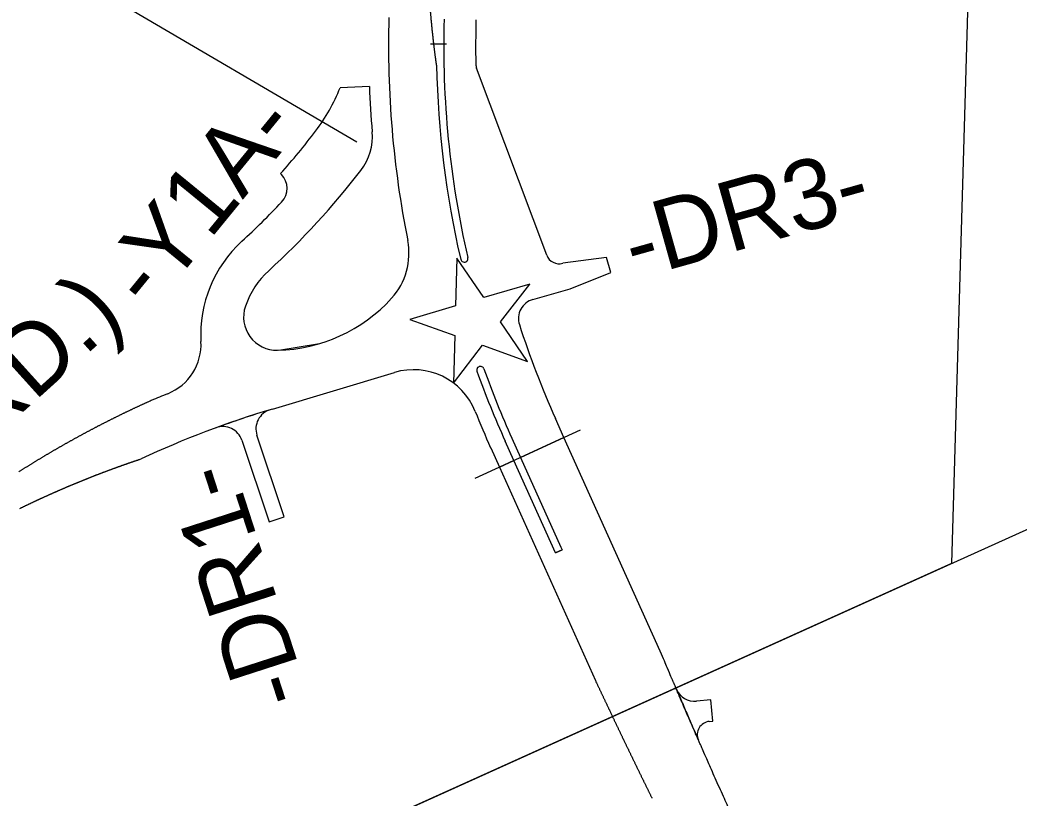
# Model space of a CAD drawing. Extents: x 2094564 to 2100382, y 679033 to 692366.
# Drawn here: x 2097390 to 2098142, y 685528 to 686113 of the extents above; entities that cross this region are included whole.
import ezdxf

# ---------------------------------------------------------------- set-up
doc = ezdxf.new("R2010")
doc.units = 0
for name, color, linetype in [('Pattern 17', 7, 'Continuous'), ('Prop RDY Traffic Signal CELL', 7, 'Continuous'), ('Prop Shade Light', 7, 'Continuous'), ('Scratch_Level_0', 7, 'Continuous'), ('Scratch_Level_1', 7, 'Continuous'), ('Scratch_Level_3', 7, 'Continuous')]:
    doc.layers.add(name, color=color, linetype=linetype)

msp = doc.modelspace()

# ---------------------------------------------------------------- linework, layer by layer
at = {"layer": 'Pattern 17'}
for points in [[(2098090.85, 685704.42), (2097236.93, 685318.96), (2097029.37, 685324.99), (2097061.33, 686424.42), (2097067.15, 686624.39), (2097093.39, 686623.63), (2097228.13, 686619.71), (2097231.42, 686732.99), (2098120, 686707.16)], [(2098911.14, 684517.12), (2097955.44, 684082.23), (2097499.89, 685083.35), (2097417.03, 685265.44), (2097440.93, 685276.32), (2097563.62, 685332.14), (2097512.93, 685443.54), (2098323.16, 685809.28)]]:
    msp.add_lwpolyline(points, close=True, dxfattribs=at)
at = {"layer": 'Prop RDY Traffic Signal CELL'}
msp.add_lwpolyline([(2097739.08, 685904.5), (2097718.8, 685934.13), (2097717.79, 685898.24), (2097683.27, 685888.09), (2097717.17, 685876.01), (2097716.16, 685840.07), (2097738.1, 685868.55), (2097771.95, 685856.48), (2097751.65, 685886.14), (2097773.61, 685914.65), (2097739.08, 685904.5)], dxfattribs=at)
at = {"layer": 'Prop Shade Light'}
for p, q in [((2097786.31, 685936.39), (2097733.62, 686076.93)), ((2097652.95, 686063.22), (2097630.92, 686062.34)), ((2097586.14, 685997.68), (2097586.79, 685997)), ((2097831.27, 685934.7), (2097798.4, 685930.28)), ((2097834.47, 685923.42), (2097831.27, 685934.7)), ((2097803.86, 685911.04), (2097834.47, 685923.42)), ((2097775.95, 685903.12), (2097803.86, 685911.04)), ((2097584.79, 685864.84), (2097615.37, 685869.82)), ((2097580, 685820.61), (2097671.8, 685848.08)), ((2097799.34, 685799.25), (2097792.96, 685813.43)), ((2097556.97, 685797.17), (2097577.46, 685735.81)), ((2097588.84, 685739.61), (2097568.35, 685800.97)), ((2097761.62, 685781.95), (2097755.12, 685796.4)), ((2097760.13, 685798.66), (2097766.62, 685784.24)), ((2097799.34, 685799.25), (2097766.62, 685784.24)), ((2097766.62, 685784.24), (2097799.34, 685799.25)), ((2097871.74, 685638.39), (2097799.34, 685799.25)), ((2097744.18, 685791.48), (2097750.72, 685776.94)), ((2097761.62, 685781.95), (2097750.72, 685776.94)), ((2097750.72, 685776.94), (2097761.62, 685781.95)), ((2097792.84, 685712.58), (2097761.62, 685781.95)), ((2097766.62, 685784.24), (2097797.05, 685716.63)), ((2097750.72, 685776.94), (2097822.96, 685616.43)), ((2097577.46, 685735.81), (2097588.84, 685739.61)), ((2097797.87, 685714.8), (2097792.84, 685712.58)), ((2097797.05, 685716.63), (2097797.87, 685714.8)), ((2097909.76, 685601.83), (2097899.1, 685600.84)), ((2097911.25, 685585.9), (2097909.76, 685601.83)), ((2097908.66, 685585.66), (2097911.25, 685585.9))]:
    msp.add_line(p, q, dxfattribs=at)
msp.add_lwpolyline([(2097646.53, 686000.13), (2097646.53, 686000.13)], dxfattribs=at)
for centre, radius, start, end in [((2098415.1, 686093.44), 747.75, 178.33483, 191.26257), ((2098415.1, 686093.44), 706.25, 178.33483, 193.00645), ((2098415.1, 686093.44), 682.25, 178.33483, 181.10817), ((2098415.1, 686093.44), 711.75, 181.14892, 193.00593), ((2097742.98, 686080.44), 10, 181.10817, 200.55266), ((2097503.07, 686112.96), 137.5, 322.71885, 338.39952), ((2098415.1, 686093.44), 762.75, 182.27079, 184.83226), ((2097180.74, 686358.34), 542.6, 318.34184, 322.71885), ((2097613.34, 686025.66), 41.88, 322.43812, 4.83226), ((2097180.74, 686358.34), 587.6, 312.43424, 322.43799), ((2097575.99, 685986.59), 15, 316.75473, 43.94176), ((2097180.74, 686358.34), 557.6, 312.43424, 316.75473), ((2097621.08, 685876.69), 95, 132.43424, 183.15611), ((2097632.72, 685937.63), 50, 317.65988, 11.26257), ((2097724.29, 685933.87), 2.75, 192.87166, 13.00645), ((2097795.67, 685939.9), 10, 200.55266, 285.83492), ((2097621.08, 685876.69), 65, 132.43424, 160.85001), ((2097580.98, 685984.78), 120, 271.39981, 317.65988), ((2097780.05, 685888.69), 15, 105.83492, 197.86981), ((2097583.3, 685889.81), 25, 160.85001, 271.39981), ((2098415.1, 686093.44), 682.25, 197.86981, 204.23092), ((2097486.29, 685869.26), 40, 291.99663, 3.15611), ((2097686.13, 685800.18), 50, 21.91468, 106.65716), ((2097736.46, 685849.97), 2.75, 19.63206, 199.73603), ((2098415.1, 686093.44), 723.75, 199.73603, 204.23092), ((2098415.1, 686093.44), 718.25, 199.73643, 204.23092), ((2097791.55, 685113.58), 775, 111.99663, 112.98788), ((2097791.55, 685113.58), 738, 106.65716, 114.87261), ((2097791.55, 685113.58), 738, 106.80013, 110.12898), ((2097582.58, 685805.72), 15, 106.80013, 198.46455), ((2098415.1, 686093.44), 735.75, 201.91468, 204.23092), ((2097542.74, 685792.42), 15, 18.46455, 110.12898), ((2097897.7, 685615.77), 15, 203.16029, 275.3551), ((2097909.59, 685575.7), 10, 95.3551, 203.63261)]:
    msp.add_arc(centre, radius, start, end, dxfattribs=at)
for points in [[(2097699.61, 686112.47), (2097699.57, 686112.91), (2097699.5, 686113.58), (2097699.44, 686114.26), (2097699.38, 686114.94), (2097699.32, 686115.62), (2097699.26, 686116.3), (2097699.2, 686116.97), (2097699.13, 686117.65), (2097699.07, 686118.33), (2097699.01, 686119.01), (2097698.95, 686119.68), (2097698.89, 686120.36), (2097698.83, 686121.04), (2097698.77, 686121.72), (2097698.7, 686122.4), (2097698.64, 686123.07), (2097698.58, 686123.75), (2097698.52, 686124.43), (2097698.46, 686125.11), (2097698.4, 686125.78), (2097698.34, 686126.46), (2097698.27, 686127.14), (2097698.21, 686127.82), (2097698.15, 686128.49), (2097698.09, 686129.17)], [(2097701.35, 686095.8), (2097701.33, 686095.99), (2097701.25, 686096.66), (2097701.18, 686097.34), (2097701.1, 686098.01), (2097701.02, 686098.69), (2097700.95, 686099.37), (2097700.87, 686100.04), (2097700.8, 686100.72), (2097700.72, 686101.39), (2097700.65, 686102.07), (2097700.58, 686102.74), (2097700.51, 686103.42), (2097700.43, 686104.1), (2097700.36, 686104.77), (2097700.29, 686105.45), (2097700.22, 686106.13), (2097700.16, 686106.81), (2097700.09, 686107.48), (2097700.02, 686108.16), (2097699.95, 686108.84), (2097699.89, 686109.51), (2097699.82, 686110.19), (2097699.76, 686110.87), (2097699.69, 686111.55), (2097699.63, 686112.23), (2097699.61, 686112.47)], [(2097703.5, 686079.17), (2097703.4, 686079.84), (2097703.31, 686080.51), (2097703.22, 686081.18), (2097703.12, 686081.85), (2097703.03, 686082.52), (2097702.94, 686083.2), (2097702.85, 686083.87), (2097702.76, 686084.54), (2097702.67, 686085.21), (2097702.58, 686085.88), (2097702.5, 686086.56), (2097702.41, 686087.23), (2097702.32, 686087.9), (2097702.24, 686088.58), (2097702.15, 686089.25), (2097702.07, 686089.92), (2097701.98, 686090.6), (2097701.9, 686091.27), (2097701.82, 686091.94), (2097701.73, 686092.62), (2097701.65, 686093.29), (2097701.57, 686093.97), (2097701.49, 686094.64), (2097701.41, 686095.31), (2097701.35, 686095.8)], [(2097488.88, 685827.04), (2097487.21, 685826.29), (2097486.37, 685825.91), (2097485.53, 685825.53), (2097484.69, 685825.15), (2097483.86, 685824.77), (2097483.02, 685824.39), (2097482.19, 685824), (2097481.35, 685823.62), (2097480.52, 685823.24), (2097479.69, 685822.85), (2097478.85, 685822.46), (2097478.02, 685822.08), (2097477.19, 685821.69), (2097476.36, 685821.3), (2097475.52, 685820.91), (2097474.69, 685820.51), (2097473.86, 685820.12), (2097473.03, 685819.73), (2097472.2, 685819.33), (2097471.37, 685818.94), (2097470.55, 685818.54), (2097469.72, 685818.15), (2097468.89, 685817.75), (2097468.35, 685817.49)], [(2097468.35, 685817.49), (2097468.06, 685817.35), (2097467.24, 685816.95), (2097466.41, 685816.55), (2097465.59, 685816.14), (2097464.76, 685815.74), (2097463.94, 685815.34), (2097463.11, 685814.93), (2097462.29, 685814.52), (2097461.47, 685814.12), (2097460.64, 685813.71), (2097459.82, 685813.3), (2097459, 685812.89), (2097458.18, 685812.48), (2097457.36, 685812.07), (2097456.54, 685811.65), (2097455.72, 685811.24), (2097454.9, 685810.83), (2097454.08, 685810.41), (2097453.26, 685809.99), (2097452.45, 685809.58), (2097451.63, 685809.16), (2097450.81, 685808.74), (2097450, 685808.32), (2097449.18, 685807.9), (2097448.37, 685807.47), (2097448.11, 685807.34)], [(2097448.11, 685807.34), (2097447.55, 685807.05), (2097446.74, 685806.63), (2097445.93, 685806.2), (2097445.11, 685805.77), (2097444.3, 685805.35), (2097443.49, 685804.92), (2097442.68, 685804.49), (2097441.87, 685804.06), (2097441.06, 685803.63), (2097440.25, 685803.2), (2097439.44, 685802.76), (2097438.63, 685802.33), (2097437.82, 685801.89), (2097437.01, 685801.46), (2097436.21, 685801.02), (2097435.4, 685800.58), (2097434.6, 685800.15), (2097433.79, 685799.71), (2097432.99, 685799.27), (2097432.18, 685798.82), (2097431.38, 685798.38), (2097430.57, 685797.94), (2097429.77, 685797.49), (2097428.97, 685797.05), (2097428.17, 685796.6)], [(2097428.17, 685796.6), (2097427.37, 685796.16), (2097426.57, 685795.71), (2097425.77, 685795.26), (2097424.97, 685794.81), (2097424.17, 685794.36), (2097423.37, 685793.91), (2097422.57, 685793.45), (2097421.78, 685793), (2097420.98, 685792.54), (2097420.18, 685792.09), (2097419.39, 685791.63), (2097418.59, 685791.17), (2097417.8, 685790.72), (2097417.01, 685790.26), (2097416.21, 685789.8), (2097415.42, 685789.34), (2097414.63, 685788.87), (2097413.84, 685788.41), (2097413.05, 685787.95), (2097412.26, 685787.48), (2097411.47, 685787.02), (2097410.68, 685786.55), (2097409.89, 685786.08), (2097409.1, 685785.61), (2097408.59, 685785.31)], [(2097408.59, 685785.31), (2097408.31, 685785.14), (2097407.53, 685784.67), (2097406.74, 685784.2), (2097405.95, 685783.73), (2097405.17, 685783.26), (2097404.39, 685782.78), (2097403.6, 685782.31), (2097402.82, 685781.83), (2097402.03, 685781.36), (2097401.25, 685780.88), (2097400.47, 685780.4), (2097399.69, 685779.92), (2097398.91, 685779.44), (2097398.13, 685778.96), (2097397.35, 685778.47), (2097396.57, 685777.99), (2097395.79, 685777.51), (2097395.02, 685777.02), (2097394.24, 685776.54), (2097393.46, 685776.05), (2097392.69, 685775.56), (2097391.91, 685775.07), (2097391.14, 685774.58), (2097390.36, 685774.09), (2097389.59, 685773.6), (2097389.34, 685773.44)], [(2097465.69, 685777.79), (2097466.14, 685777.96), (2097466.77, 685778.18), (2097467.39, 685778.4), (2097468.02, 685778.62), (2097468.64, 685778.84), (2097469.26, 685779.06), (2097469.89, 685779.28), (2097470.51, 685779.5), (2097471.14, 685779.72), (2097471.76, 685779.94), (2097472.39, 685780.15), (2097473.01, 685780.37), (2097473.63, 685780.59), (2097474.26, 685780.8), (2097474.89, 685781.02), (2097475.51, 685781.23), (2097476.14, 685781.44), (2097476.76, 685781.66), (2097477.39, 685781.87), (2097478.01, 685782.08), (2097478.64, 685782.29), (2097479.26, 685782.5), (2097479.89, 685782.71), (2097481.14, 685783.13)], [(2097450.36, 685772.12), (2097450.61, 685772.21), (2097451.23, 685772.45), (2097451.85, 685772.68), (2097452.47, 685772.92), (2097453.09, 685773.15), (2097453.71, 685773.39), (2097454.33, 685773.62), (2097454.95, 685773.86), (2097455.57, 685774.09), (2097456.19, 685774.32), (2097456.81, 685774.55), (2097457.43, 685774.78), (2097458.05, 685775.01), (2097458.67, 685775.24), (2097459.3, 685775.47), (2097459.92, 685775.7), (2097460.54, 685775.93), (2097461.16, 685776.16), (2097461.78, 685776.38), (2097462.41, 685776.61), (2097463.03, 685776.84), (2097463.65, 685777.06), (2097464.28, 685777.29), (2097464.9, 685777.51), (2097465.52, 685777.73), (2097465.69, 685777.79)], [(2097419.99, 685759.7), (2097420.43, 685759.9), (2097421.04, 685760.16), (2097421.66, 685760.43), (2097422.27, 685760.69), (2097422.88, 685760.95), (2097423.49, 685761.22), (2097424.11, 685761.48), (2097424.72, 685761.74), (2097425.33, 685762), (2097425.94, 685762.26), (2097426.56, 685762.52), (2097427.17, 685762.78), (2097427.78, 685763.04), (2097428.4, 685763.3), (2097429.01, 685763.56), (2097429.63, 685763.81), (2097430.24, 685764.07), (2097430.86, 685764.33), (2097431.47, 685764.58), (2097432.08, 685764.84), (2097432.7, 685765.09), (2097433.32, 685765.34), (2097433.93, 685765.6), (2097434.55, 685765.85), (2097435.16, 685766.1)], [(2097435.16, 685766.1), (2097435.78, 685766.35), (2097436.39, 685766.6), (2097437.01, 685766.85), (2097437.63, 685767.1), (2097438.24, 685767.35), (2097438.86, 685767.6), (2097439.48, 685767.85), (2097440.09, 685768.1), (2097440.71, 685768.34), (2097441.33, 685768.59), (2097441.94, 685768.83), (2097442.56, 685769.08), (2097443.18, 685769.32), (2097443.8, 685769.57), (2097444.42, 685769.81), (2097445.03, 685770.05), (2097445.65, 685770.3), (2097446.27, 685770.54), (2097446.89, 685770.78), (2097447.51, 685771.02), (2097448.13, 685771.26), (2097448.75, 685771.5), (2097449.37, 685771.74), (2097449.99, 685771.97), (2097450.36, 685772.12)], [(2097404.96, 685752.97), (2097405.2, 685753.08), (2097405.81, 685753.36), (2097406.41, 685753.64), (2097407.02, 685753.92), (2097407.63, 685754.19), (2097408.24, 685754.47), (2097408.84, 685754.75), (2097409.45, 685755.02), (2097410.06, 685755.3), (2097410.67, 685755.57), (2097411.28, 685755.85), (2097411.89, 685756.12), (2097412.5, 685756.4), (2097413.11, 685756.67), (2097413.72, 685756.94), (2097414.33, 685757.21), (2097414.94, 685757.48), (2097415.55, 685757.75), (2097416.16, 685758.02), (2097416.77, 685758.29), (2097417.38, 685758.56), (2097417.99, 685758.83), (2097418.6, 685759.1), (2097419.21, 685759.36), (2097419.82, 685759.63), (2097419.99, 685759.7)], [(2097390.09, 685745.9), (2097390.69, 685746.2), (2097391.29, 685746.49), (2097391.89, 685746.78), (2097392.5, 685747.08), (2097393.1, 685747.37), (2097393.7, 685747.66), (2097394.31, 685747.95), (2097394.91, 685748.24), (2097395.51, 685748.53), (2097396.12, 685748.82), (2097396.72, 685749.1), (2097397.33, 685749.39), (2097397.93, 685749.68), (2097398.53, 685749.97), (2097399.14, 685750.25), (2097399.74, 685750.54), (2097400.35, 685750.82), (2097400.96, 685751.11), (2097401.56, 685751.39), (2097402.17, 685751.67), (2097402.77, 685751.96), (2097403.38, 685752.24), (2097403.99, 685752.52), (2097404.59, 685752.8), (2097404.96, 685752.97)], [(2097822.96, 685616.43), (2097823.81, 685614.64), (2097824.23, 685613.74), (2097824.66, 685612.85), (2097825.08, 685611.95), (2097825.51, 685611.06), (2097825.93, 685610.16), (2097826.35, 685609.27), (2097826.78, 685608.37), (2097827.2, 685607.47), (2097827.63, 685606.58), (2097828.05, 685605.68), (2097828.48, 685604.79), (2097828.9, 685603.89), (2097829.33, 685603), (2097829.75, 685602.1), (2097830.18, 685601.21), (2097830.6, 685600.31), (2097831.03, 685599.41), (2097831.45, 685598.52), (2097831.88, 685597.62), (2097832.3, 685596.73), (2097832.73, 685595.83), (2097833.15, 685594.94), (2097833.46, 685594.28)], [(2097833.46, 685594.28), (2097833.58, 685594.04), (2097834, 685593.14), (2097834.43, 685592.24), (2097834.86, 685591.34), (2097835.28, 685590.44), (2097835.71, 685589.54), (2097836.14, 685588.65), (2097836.56, 685587.75), (2097836.99, 685586.85), (2097837.42, 685585.95), (2097837.85, 685585.05), (2097838.28, 685584.15), (2097838.7, 685583.26), (2097839.13, 685582.36), (2097839.56, 685581.46), (2097839.99, 685580.56), (2097840.42, 685579.66), (2097840.85, 685578.77), (2097841.28, 685577.87), (2097841.71, 685576.97), (2097842.14, 685576.07), (2097842.57, 685575.18), (2097843, 685574.28), (2097843.43, 685573.38), (2097843.86, 685572.48), (2097844.02, 685572.16)], [(2097844.02, 685572.16), (2097844.29, 685571.59), (2097844.72, 685570.69), (2097845.15, 685569.79), (2097845.58, 685568.9), (2097846.01, 685568), (2097846.45, 685567.1), (2097846.88, 685566.21), (2097847.31, 685565.31), (2097847.74, 685564.41), (2097848.17, 685563.52), (2097848.61, 685562.62), (2097849.04, 685561.72), (2097849.47, 685560.83), (2097849.91, 685559.93), (2097850.34, 685559.04), (2097850.77, 685558.14), (2097851.21, 685557.25), (2097851.64, 685556.35), (2097852.07, 685555.45), (2097852.51, 685554.56), (2097852.94, 685553.66), (2097853.38, 685552.77), (2097853.81, 685551.87), (2097854.25, 685550.98), (2097854.68, 685550.08)], [(2097854.68, 685550.08), (2097855.12, 685549.19), (2097855.55, 685548.29), (2097855.99, 685547.4), (2097856.42, 685546.51), (2097856.86, 685545.61), (2097857.29, 685544.72), (2097857.73, 685543.82), (2097858.17, 685542.93), (2097858.6, 685542.03), (2097859.04, 685541.14), (2097859.48, 685540.25), (2097859.91, 685539.35), (2097860.35, 685538.46), (2097860.79, 685537.56), (2097861.23, 685536.67), (2097861.66, 685535.78), (2097862.1, 685534.88), (2097862.54, 685533.99), (2097862.98, 685533.1), (2097863.42, 685532.2), (2097863.85, 685531.31), (2097864.29, 685530.42), (2097864.73, 685529.53), (2097865.17, 685528.63), (2097865.46, 685528.04)]]:
    msp.add_spline(points, degree=3, dxfattribs=at)
for points in [[(2097900.7, 685571.08), (2097900.55, 685571.42), (2097900.4, 685571.77), (2097900.17, 685572.3), (2097900.07, 685572.51), (2097899.98, 685572.73), (2097899.94, 685572.82), (2097899.92, 685572.86), (2097899.86, 685572.99), (2097899.52, 685573.78), (2097898.57, 685575.95), (2097896.44, 685580.83), (2097892.2, 685590.59), (2097887.38, 685601.76), (2097883.72, 685610.32), (2097882.45, 685613.29), (2097882.3, 685613.64), (2097882.22, 685613.81), (2097882, 685614.34), (2097881.7, 685615.04), (2097881.4, 685615.74), (2097881.1, 685616.44), (2097880.95, 685616.79), (2097880.21, 685618.54), (2097877.22, 685625.55), (2097874.23, 685632.56), (2097871.74, 685638.39)], [(2097883.91, 685609.87), (2097884.67, 685608.1), (2097887.82, 685600.74), (2097892.2, 685590.59), (2097896.44, 685580.83), (2097898.57, 685575.95), (2097899.52, 685573.78), (2097899.86, 685572.99), (2097899.92, 685572.86), (2097899.94, 685572.82), (2097899.98, 685572.73), (2097900.07, 685572.51), (2097900.17, 685572.3), (2097900.3, 685571.98), (2097900.37, 685571.84), (2097900.43, 685571.7)], [(2097930.43, 685504.52), (2097930.27, 685504.86), (2097930.12, 685505.21), (2097929.88, 685505.72), (2097929.78, 685505.94), (2097929.68, 685506.16), (2097929.64, 685506.24), (2097929.62, 685506.29), (2097929.56, 685506.42), (2097929.21, 685507.19), (2097928.23, 685509.35), (2097926.03, 685514.19), (2097921.65, 685523.88), (2097915.43, 685537.74), (2097909.26, 685551.61), (2097904.97, 685561.34), (2097902.84, 685566.21), (2097901.92, 685568.29), (2097901.31, 685569.68), (2097901.01, 685570.38), (2097900.7, 685571.08)]]:
    msp.add_open_spline(points, degree=3, dxfattribs=at)
at = {"layer": 'Scratch_Level_0'}
msp.add_line((2097643.38, 686021.47), (2096634.8, 686612.21), dxfattribs=at)
at = {"layer": 'Scratch_Level_1'}
for p, q in [((2097698.91, 686095.32), (2097710.91, 686095.33)), ((2097732.49, 685768.58), (2097811.64, 685804.89))]:
    msp.add_line(p, q, dxfattribs=at)
at = {"layer": 'Scratch_Level_3'}
msp.add_line((2097792.84, 685712.58), (2097797.87, 685714.8), dxfattribs=at)

# ---------------------------------------------------------------- texts
at = {"layer": 'Scratch_Level_0'}
for s, height, rotation, p in [('-Y1A-', 52.563, 50.73561, (2097488.36, 685893.14)), ('-DR3-', 52.563, 15.66184, (2097852.42, 685918)), ('(OLD STAGE RD.)', 52.5626, 42.07005, (2097032.46, 685493.43)), ('-DR1-', 52.563, 107.93388, (2097607.22, 685605))]:
    msp.add_text(s, height=height, rotation=rotation, dxfattribs=at).set_placement(p)

doc.saveas('drawing.dxf')
